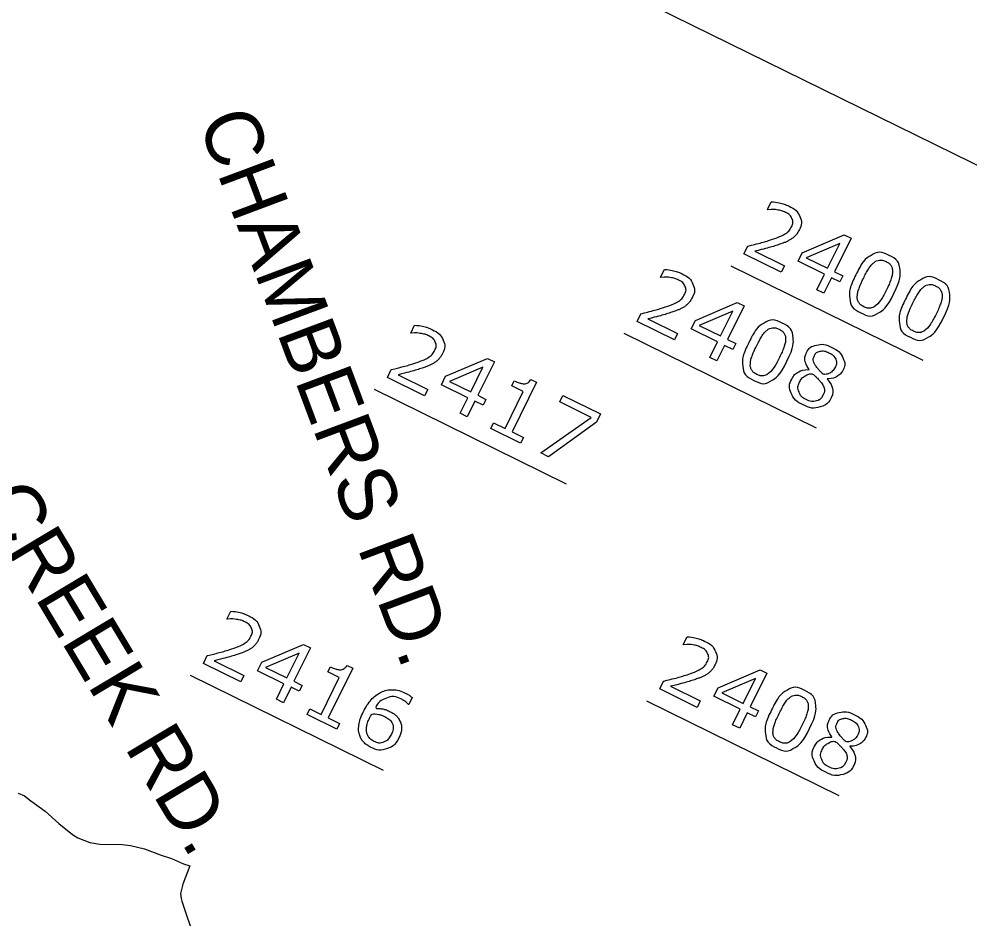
# Model space of a CAD drawing. Extents: x 1428128 to 1430390, y 857947 to 859822.
# Drawn here: x 1429189.4 to 1429305.6, y 859325.3 to 859435.3 of the extents above; entities that cross this region are included whole.
import ezdxf

# ---------------------------------------------------------------- set-up
doc = ezdxf.new("R2010")
doc.units = 0
doc.layers.add('Old_Level_1', color=7, linetype='Continuous')
doc.layers.add('Sheet Title CELL', color=7, linetype='Continuous')

msp = doc.modelspace()

# ---------------------------------------------------------------- linework, layer by layer
at = {"layer": 'Old_Level_1'}
for p, q in [((1429276.44, 859405.17), (1429299.9, 859393.63)), ((1429263.36, 859396.9), (1429286.88, 859385.33)), ((1429232.83, 859390.07), (1429256.32, 859378.51)), ((1429210.35, 859355.11), (1429233.92, 859343.51)), ((1429266.13, 859351.99), (1429289.65, 859340.41))]:
    msp.add_line(p, q, dxfattribs=at)
for points in [[(1429280.96, 859412.01), (1429280.92, 859412.03), (1429281.38, 859412.98)], [(1429289.75, 859403.2), (1429288.75, 859403.69), (1429287.82, 859401.8), (1429286.95, 859402.23), (1429287.89, 859404.12), (1429284.66, 859405.71), (1429285.17, 859406.75), (1429290.3, 859408.94), (1429291.13, 859408.53), (1429289.11, 859404.42), (1429290.11, 859403.93), (1429289.75, 859403.2)], [(1429288.24, 859404.85), (1429289.74, 859407.88), (1429285.63, 859406.13), (1429288.24, 859404.85)], [(1429282.6, 859404.37), (1429278.04, 859406.61), (1429278.51, 859407.56)], [(1429279.36, 859406.93), (1429282.99, 859405.15), (1429282.6, 859404.37)], [(1429267.89, 859403.74), (1429267.84, 859403.76), (1429268.31, 859404.71)], [(1429276.68, 859394.93), (1429275.68, 859395.42), (1429274.74, 859393.53), (1429273.88, 859393.96), (1429274.81, 859395.85), (1429271.58, 859397.44), (1429272.1, 859398.48), (1429277.22, 859400.67), (1429278.06, 859400.26), (1429276.03, 859396.15), (1429277.03, 859395.66), (1429276.68, 859394.93)], [(1429269.53, 859396.1), (1429264.97, 859398.34), (1429265.44, 859399.29)], [(1429266.29, 859398.66), (1429269.91, 859396.88), (1429269.53, 859396.1)], [(1429275.17, 859396.58), (1429276.66, 859399.62), (1429272.56, 859397.86), (1429275.17, 859396.58)], [(1429237.36, 859396.91), (1429237.31, 859396.93), (1429237.78, 859397.88)], [(1429246.15, 859388.1), (1429245.15, 859388.59), (1429244.21, 859386.7), (1429243.35, 859387.12), (1429244.28, 859389.02), (1429241.05, 859390.61), (1429241.57, 859391.65), (1429246.69, 859393.84), (1429247.53, 859393.43), (1429245.5, 859389.32), (1429246.5, 859388.83), (1429246.15, 859388.1)], [(1429244.64, 859389.75), (1429246.13, 859392.78), (1429242.03, 859391.03), (1429244.64, 859389.75)], [(1429239, 859389.26), (1429234.44, 859391.51), (1429234.91, 859392.46)], [(1429235.76, 859391.83), (1429239.38, 859390.04), (1429239, 859389.26)], [(1429285.99, 859392.46), (1429286.01, 859392.48)], [(1429250.74, 859383.49), (1429247.1, 859385.28), (1429247.43, 859385.97), (1429248.84, 859385.28), (1429251.05, 859389.79), (1429249.65, 859390.48), (1429249.96, 859391.09)], [(1429251.99, 859391.26), (1429252.69, 859390.91), (1429249.7, 859384.85), (1429251.08, 859384.17), (1429250.74, 859383.49)], [(1429288.23, 859391.35), (1429288.21, 859391.32)], [(1429260.02, 859386.03), (1429254.16, 859381.8), (1429253.19, 859382.28), (1429259.35, 859386.63), (1429255.52, 859388.51), (1429255.91, 859389.3), (1429260.51, 859387.04), (1429260.02, 859386.03)], [(1429214.88, 859361.95), (1429214.83, 859361.97), (1429215.3, 859362.92)], [(1429270.66, 859358.83), (1429270.61, 859358.85), (1429271.08, 859359.8)], [(1429223.67, 859353.14), (1429222.67, 859353.63), (1429221.73, 859351.74), (1429220.87, 859352.17), (1429221.8, 859354.06), (1429218.57, 859355.65), (1429219.08, 859356.69), (1429224.21, 859358.88), (1429225.04, 859358.47), (1429223.02, 859354.36), (1429224.02, 859353.87), (1429223.67, 859353.14)], [(1429216.52, 859354.31), (1429211.96, 859356.55), (1429212.43, 859357.5)], [(1429213.28, 859356.87), (1429216.9, 859355.09), (1429216.52, 859354.31)], [(1429222.15, 859354.79), (1429223.65, 859357.82), (1429219.54, 859356.07), (1429222.15, 859354.79)], [(1429228.26, 859348.53), (1429224.62, 859350.32), (1429224.95, 859351.01), (1429226.35, 859350.32), (1429228.57, 859354.83), (1429227.17, 859355.52), (1429227.48, 859356.13)], [(1429229.51, 859356.3), (1429230.21, 859355.95), (1429227.22, 859349.89), (1429228.6, 859349.21), (1429228.26, 859348.53)], [(1429279.45, 859350.02), (1429278.45, 859350.51), (1429277.52, 859348.62), (1429276.65, 859349.04), (1429277.58, 859350.94), (1429274.36, 859352.53), (1429274.87, 859353.56), (1429280, 859355.76), (1429280.83, 859355.35), (1429278.81, 859351.24), (1429279.81, 859350.74), (1429279.45, 859350.02)], [(1429272.3, 859351.18), (1429267.74, 859353.43), (1429268.21, 859354.38)], [(1429277.94, 859351.66), (1429279.43, 859354.7), (1429275.33, 859352.95), (1429277.94, 859351.66)], [(1429269.06, 859353.75), (1429272.68, 859351.96), (1429272.3, 859351.18)], [(1429237.47, 859352.38), (1429237.05, 859351.51), (1429237, 859351.53)], [(1429288.77, 859347.54), (1429288.78, 859347.57)], [(1429291, 859346.43), (1429290.98, 859346.41)]]:
    msp.add_lwpolyline(points, dxfattribs=at)
for points in [[(1429281.38, 859412.98), (1429281.78, 859412.98), (1429282.38, 859412.85), (1429282.98, 859412.71), (1429283.49, 859412.47), (1429284.52, 859411.96), (1429284.87, 859411.17), (1429285.21, 859410.38), (1429284.79, 859409.53), (1429284.6, 859409.14), (1429284.34, 859408.86), (1429284.08, 859408.57), (1429283.74, 859408.37), (1429283.43, 859408.18), (1429283.06, 859408.02), (1429282.69, 859407.87), (1429282.19, 859407.71), (1429281.47, 859407.47), (1429280.73, 859407.28), (1429280, 859407.09), (1429279.36, 859406.93)], [(1429278.51, 859407.56), (1429279.19, 859407.73), (1429279.87, 859407.9), (1429280.54, 859408.08), (1429281.15, 859408.28), (1429282.44, 859408.69), (1429283, 859409.02), (1429283.57, 859409.36), (1429283.85, 859409.93), (1429284.11, 859410.46), (1429283.91, 859410.92), (1429283.71, 859411.39), (1429283.08, 859411.7), (1429282.67, 859411.9), (1429282.12, 859411.99), (1429281.57, 859412.08), (1429280.96, 859412.01)], [(1429296.38, 859401.77), (1429295.48, 859399.96), (1429294.5, 859399.39), (1429293.51, 859398.82), (1429292.32, 859399.41), (1429291.11, 859400), (1429290.98, 859401.14), (1429290.84, 859402.27), (1429291.72, 859404.05), (1429292.6, 859405.85), (1429293.59, 859406.43), (1429294.58, 859407.01), (1429295.77, 859406.42), (1429296.98, 859405.83), (1429297.11, 859404.68), (1429297.24, 859403.53), (1429296.38, 859401.77)], [(1429294.18, 859400.3), (1429294.52, 859400.59), (1429294.82, 859401.06), (1429295.12, 859401.53), (1429295.46, 859402.22), (1429295.8, 859402.91), (1429295.99, 859403.45), (1429296.18, 859403.98), (1429296.19, 859404.41), (1429296.21, 859404.84), (1429296.02, 859405.15), (1429295.84, 859405.46), (1429295.41, 859405.67), (1429294.98, 859405.88), (1429294.62, 859405.84), (1429294.25, 859405.8), (1429293.91, 859405.53), (1429293.6, 859405.27), (1429293.27, 859404.76), (1429292.95, 859404.25), (1429292.64, 859403.6), (1429292.29, 859402.9), (1429292.11, 859402.4), (1429291.92, 859401.9), (1429291.9, 859401.44), (1429291.87, 859401.02), (1429292.06, 859400.7), (1429292.24, 859400.38), (1429292.69, 859400.15), (1429293.11, 859399.94), (1429293.48, 859399.98), (1429293.85, 859400.02), (1429294.18, 859400.3)], [(1429268.31, 859404.71), (1429268.71, 859404.71), (1429269.31, 859404.58), (1429269.91, 859404.45), (1429270.41, 859404.2), (1429271.45, 859403.69), (1429271.79, 859402.9), (1429272.13, 859402.11), (1429271.71, 859401.26), (1429271.52, 859400.87), (1429271.26, 859400.59), (1429271, 859400.31), (1429270.67, 859400.1), (1429270.35, 859399.91), (1429269.98, 859399.75), (1429269.61, 859399.6), (1429269.11, 859399.44), (1429268.39, 859399.2), (1429267.66, 859399.01), (1429266.92, 859398.82), (1429266.29, 859398.66)], [(1429265.44, 859399.29), (1429266.11, 859399.46), (1429266.79, 859399.64), (1429267.47, 859399.81), (1429268.08, 859400.01), (1429269.36, 859400.42), (1429269.93, 859400.75), (1429270.49, 859401.09), (1429270.77, 859401.66), (1429271.03, 859402.19), (1429270.83, 859402.66), (1429270.63, 859403.12), (1429270.01, 859403.43), (1429269.6, 859403.63), (1429269.04, 859403.72), (1429268.49, 859403.81), (1429267.89, 859403.74)], [(1429302.44, 859398.79), (1429301.55, 859396.98), (1429300.56, 859396.41), (1429299.58, 859395.84), (1429298.39, 859396.42), (1429297.17, 859397.02), (1429297.04, 859398.15), (1429296.91, 859399.29), (1429297.78, 859401.07), (1429298.67, 859402.87), (1429299.65, 859403.45), (1429300.64, 859404.03), (1429301.84, 859403.44), (1429303.05, 859402.84), (1429303.18, 859401.7), (1429303.31, 859400.55), (1429302.44, 859398.79)], [(1429300.24, 859397.32), (1429300.58, 859397.61), (1429300.88, 859398.08), (1429301.18, 859398.54), (1429301.52, 859399.24), (1429301.86, 859399.93), (1429302.05, 859400.46), (1429302.25, 859401), (1429302.26, 859401.43), (1429302.27, 859401.86), (1429302.08, 859402.17), (1429301.9, 859402.48), (1429301.47, 859402.69), (1429301.04, 859402.9), (1429300.68, 859402.86), (1429300.32, 859402.82), (1429299.98, 859402.54), (1429299.66, 859402.28), (1429299.34, 859401.77), (1429299.02, 859401.26), (1429298.7, 859400.62), (1429298.35, 859399.91), (1429298.17, 859399.41), (1429297.98, 859398.91), (1429297.96, 859398.46), (1429297.94, 859398.03), (1429298.12, 859397.71), (1429298.3, 859397.39), (1429298.75, 859397.17), (1429299.18, 859396.96), (1429299.54, 859397), (1429299.91, 859397.04), (1429300.24, 859397.32)], [(1429283.3, 859393.5), (1429282.41, 859391.69), (1429281.42, 859391.12), (1429280.44, 859390.55), (1429279.25, 859391.14), (1429278.04, 859391.73), (1429277.9, 859392.87), (1429277.77, 859394), (1429278.64, 859395.78), (1429279.53, 859397.58), (1429280.51, 859398.16), (1429281.5, 859398.74), (1429282.7, 859398.15), (1429283.91, 859397.56), (1429284.04, 859396.41), (1429284.17, 859395.26), (1429283.3, 859393.5)], [(1429237.78, 859397.88), (1429238.18, 859397.88), (1429238.78, 859397.75), (1429239.38, 859397.61), (1429239.88, 859397.37), (1429240.92, 859396.86), (1429241.26, 859396.07), (1429241.6, 859395.28), (1429241.18, 859394.43), (1429240.99, 859394.04), (1429240.73, 859393.76), (1429240.47, 859393.47), (1429240.14, 859393.27), (1429239.82, 859393.08), (1429239.45, 859392.92), (1429239.08, 859392.77), (1429238.58, 859392.61), (1429237.86, 859392.37), (1429237.13, 859392.18), (1429236.39, 859391.99), (1429235.76, 859391.83)], [(1429281.1, 859392.03), (1429281.44, 859392.32), (1429281.74, 859392.79), (1429282.04, 859393.26), (1429282.38, 859393.96), (1429282.72, 859394.64), (1429282.91, 859395.18), (1429283.11, 859395.71), (1429283.12, 859396.15), (1429283.13, 859396.57), (1429282.95, 859396.88), (1429282.76, 859397.19), (1429282.33, 859397.41), (1429281.91, 859397.61), (1429281.54, 859397.57), (1429281.18, 859397.53), (1429280.84, 859397.26), (1429280.52, 859397), (1429280.2, 859396.49), (1429279.88, 859395.98), (1429279.56, 859395.33), (1429279.21, 859394.63), (1429279.03, 859394.13), (1429278.84, 859393.63), (1429278.82, 859393.17), (1429278.8, 859392.75), (1429278.98, 859392.43), (1429279.16, 859392.11), (1429279.61, 859391.88), (1429280.04, 859391.68), (1429280.4, 859391.71), (1429280.77, 859391.75), (1429281.1, 859392.03)], [(1429234.91, 859392.46), (1429235.58, 859392.63), (1429236.26, 859392.8), (1429236.94, 859392.98), (1429237.55, 859393.17), (1429238.83, 859393.59), (1429239.4, 859393.92), (1429239.96, 859394.26), (1429240.24, 859394.83), (1429240.5, 859395.36), (1429240.3, 859395.82), (1429240.1, 859396.29), (1429239.48, 859396.6), (1429239.07, 859396.8), (1429238.51, 859396.89), (1429237.96, 859396.98), (1429237.36, 859396.91)], [(1429286.01, 859392.48), (1429285.61, 859393.04), (1429285.52, 859393.51), (1429285.42, 859393.98), (1429285.68, 859394.5), (1429286.05, 859395.26), (1429286.92, 859395.46), (1429287.8, 859395.66), (1429288.76, 859395.18), (1429289.77, 859394.69), (1429290.13, 859393.91), (1429290.5, 859393.13), (1429290.13, 859392.38), (1429289.9, 859391.93), (1429289.4, 859391.62), (1429288.9, 859391.32), (1429288.23, 859391.35)], [(1429289.23, 859392.81), (1429289.47, 859393.29), (1429289.24, 859393.76), (1429289.01, 859394.24), (1429288.43, 859394.52), (1429287.86, 859394.8), (1429287.36, 859394.71), (1429286.86, 859394.62), (1429286.64, 859394.16), (1429286.48, 859393.83), (1429286.54, 859393.5), (1429286.61, 859393.18), (1429286.89, 859392.81), (1429287.02, 859392.64), (1429287.27, 859392.36), (1429287.52, 859392.07), (1429287.77, 859391.84), (1429288.37, 859391.92), (1429288.7, 859392.15), (1429289.03, 859392.39), (1429289.23, 859392.81)], [(1429288.69, 859389), (1429288.26, 859388.13), (1429287.29, 859387.88), (1429286.33, 859387.64), (1429285.3, 859388.15), (1429284.2, 859388.68), (1429283.83, 859389.57), (1429283.46, 859390.45), (1429283.9, 859391.33), (1429284.17, 859391.89), (1429284.72, 859392.19), (1429285.27, 859392.48), (1429285.99, 859392.46)], [(1429287.72, 859389.37), (1429287.92, 859389.79), (1429287.86, 859390.13), (1429287.8, 859390.47), (1429287.39, 859390.98), (1429287.23, 859391.19), (1429287.02, 859391.4), (1429286.81, 859391.61), (1429286.46, 859391.97), (1429285.95, 859391.95), (1429285.51, 859391.69), (1429285.08, 859391.43), (1429284.85, 859390.95), (1429284.55, 859390.34), (1429284.77, 859389.74), (1429285, 859389.13), (1429285.64, 859388.81), (1429286.3, 859388.49), (1429286.87, 859388.63), (1429287.43, 859388.78), (1429287.72, 859389.37)], [(1429249.96, 859391.09), (1429250.24, 859390.95), (1429250.59, 859390.84), (1429250.94, 859390.73), (1429251.15, 859390.73), (1429251.41, 859390.74), (1429251.62, 859390.86), (1429251.82, 859390.97), (1429251.99, 859391.26)], [(1429288.21, 859391.32), (1429288.71, 859390.74), (1429288.85, 859390.17), (1429288.99, 859389.61), (1429288.69, 859389)], [(1429215.3, 859362.92), (1429215.7, 859362.92), (1429216.3, 859362.79), (1429216.9, 859362.65), (1429217.4, 859362.41), (1429218.44, 859361.9), (1429218.78, 859361.11), (1429219.12, 859360.32), (1429218.7, 859359.47), (1429218.51, 859359.08), (1429218.25, 859358.8), (1429217.99, 859358.51), (1429217.65, 859358.31), (1429217.34, 859358.12), (1429216.97, 859357.96), (1429216.6, 859357.81), (1429216.1, 859357.65), (1429215.38, 859357.41), (1429214.65, 859357.22), (1429213.91, 859357.03), (1429213.28, 859356.87)], [(1429212.43, 859357.5), (1429213.1, 859357.67), (1429213.78, 859357.84), (1429214.46, 859358.02), (1429215.07, 859358.21), (1429216.35, 859358.63), (1429216.91, 859358.96), (1429217.48, 859359.3), (1429217.76, 859359.87), (1429218.02, 859360.4), (1429217.82, 859360.86), (1429217.62, 859361.33), (1429217, 859361.64), (1429216.58, 859361.84), (1429216.03, 859361.93), (1429215.48, 859362.02), (1429214.88, 859361.95)], [(1429271.08, 859359.8), (1429271.48, 859359.8), (1429272.08, 859359.67), (1429272.68, 859359.53), (1429273.18, 859359.29), (1429274.22, 859358.78), (1429274.56, 859357.99), (1429274.9, 859357.2), (1429274.48, 859356.34), (1429274.3, 859355.96), (1429274.04, 859355.68), (1429273.77, 859355.39), (1429273.44, 859355.19), (1429273.12, 859354.99), (1429272.75, 859354.84), (1429272.38, 859354.69), (1429271.88, 859354.52), (1429271.16, 859354.29), (1429270.43, 859354.1), (1429269.69, 859353.91), (1429269.06, 859353.75)], [(1429268.21, 859354.38), (1429268.88, 859354.55), (1429269.56, 859354.72), (1429270.24, 859354.89), (1429270.85, 859355.09), (1429272.13, 859355.51), (1429272.7, 859355.84), (1429273.26, 859356.18), (1429273.55, 859356.75), (1429273.8, 859357.28), (1429273.6, 859357.74), (1429273.4, 859358.21), (1429272.78, 859358.51), (1429272.37, 859358.72), (1429271.82, 859358.81), (1429271.26, 859358.9), (1429270.66, 859358.83)], [(1429227.48, 859356.13), (1429227.76, 859355.99), (1429228.11, 859355.88), (1429228.46, 859355.77), (1429228.67, 859355.77), (1429228.93, 859355.79), (1429229.14, 859355.9), (1429229.34, 859356.02), (1429229.51, 859356.3)], [(1429235.88, 859347.49), (1429235.37, 859346.46), (1429234.38, 859346.14), (1429233.38, 859345.83), (1429232.4, 859346.31), (1429231.91, 859346.56), (1429231.57, 859346.91), (1429231.24, 859347.26), (1429231.08, 859347.72), (1429230.88, 859348.29), (1429230.97, 859349.01), (1429231.07, 859349.73), (1429231.49, 859350.6), (1429231.94, 859351.5), (1429232.47, 859352.1), (1429233, 859352.69), (1429233.69, 859353.02), (1429234.33, 859353.34), (1429235.1, 859353.32), (1429235.87, 859353.3), (1429236.71, 859352.88), (1429236.98, 859352.75), (1429237.15, 859352.64), (1429237.32, 859352.53), (1429237.47, 859352.38)], [(1429286.07, 859348.59), (1429285.18, 859346.78), (1429284.2, 859346.21), (1429283.21, 859345.64), (1429282.02, 859346.22), (1429280.81, 859346.82), (1429280.67, 859347.95), (1429280.54, 859349.09), (1429281.42, 859350.87), (1429282.3, 859352.67), (1429283.29, 859353.25), (1429284.27, 859353.83), (1429285.47, 859353.24), (1429286.68, 859352.64), (1429286.81, 859351.5), (1429286.94, 859350.35), (1429286.07, 859348.59)], [(1429237, 859351.53), (1429236.91, 859351.66), (1429236.68, 859351.85), (1429236.46, 859352.04), (1429236.19, 859352.17), (1429235.22, 859352.65), (1429234.34, 859352.32), (1429233.47, 859352), (1429232.86, 859351.01), (1429233.36, 859351.06), (1429233.78, 859351), (1429234.21, 859350.93), (1429234.69, 859350.7), (1429235.12, 859350.49), (1429235.41, 859350.25), (1429235.7, 859350.01), (1429235.92, 859349.6), (1429236.18, 859349.13), (1429236.18, 859348.61), (1429236.17, 859348.09), (1429235.88, 859347.49)], [(1429283.87, 859347.12), (1429284.21, 859347.41), (1429284.51, 859347.88), (1429284.81, 859348.35), (1429285.16, 859349.04), (1429285.49, 859349.73), (1429285.69, 859350.27), (1429285.88, 859350.8), (1429285.89, 859351.23), (1429285.9, 859351.66), (1429285.72, 859351.97), (1429285.53, 859352.28), (1429285.1, 859352.49), (1429284.68, 859352.7), (1429284.31, 859352.66), (1429283.95, 859352.62), (1429283.61, 859352.34), (1429283.29, 859352.08), (1429282.97, 859351.57), (1429282.65, 859351.06), (1429282.33, 859350.42), (1429281.99, 859349.71), (1429281.8, 859349.21), (1429281.62, 859348.72), (1429281.59, 859348.26), (1429281.57, 859347.83), (1429281.75, 859347.51), (1429281.93, 859347.19), (1429282.39, 859346.97), (1429282.81, 859346.76), (1429283.18, 859346.8), (1429283.54, 859346.84), (1429283.87, 859347.12)], [(1429234.94, 859347.9), (1429235.15, 859348.32), (1429235.16, 859348.65), (1429235.17, 859348.99), (1429234.99, 859349.33), (1429234.85, 859349.58), (1429234.62, 859349.75), (1429234.39, 859349.92), (1429234.11, 859350.05), (1429233.73, 859350.24), (1429233.36, 859350.32), (1429232.98, 859350.39), (1429232.54, 859350.37), (1429232.48, 859350.27), (1429232.43, 859350.18), (1429232.38, 859350.09), (1429232.31, 859349.95), (1429231.96, 859349.24), (1429231.91, 859348.76), (1429231.85, 859348.27), (1429231.99, 859347.9), (1429232.1, 859347.6), (1429232.3, 859347.39), (1429232.49, 859347.18), (1429232.78, 859347.04), (1429233.43, 859346.72), (1429234, 859346.93), (1429234.57, 859347.15), (1429234.94, 859347.9)], [(1429288.78, 859347.57), (1429288.38, 859348.13), (1429288.29, 859348.6), (1429288.2, 859349.07), (1429288.45, 859349.59), (1429288.82, 859350.35), (1429289.7, 859350.54), (1429290.57, 859350.74), (1429291.53, 859350.27), (1429292.54, 859349.77), (1429292.9, 859348.99), (1429293.27, 859348.21), (1429292.9, 859347.47), (1429292.68, 859347.01), (1429292.17, 859346.71), (1429291.67, 859346.41), (1429291, 859346.43)], [(1429292.01, 859347.9), (1429292.24, 859348.38), (1429292.01, 859348.85), (1429291.78, 859349.32), (1429291.2, 859349.61), (1429290.63, 859349.89), (1429290.13, 859349.8), (1429289.63, 859349.7), (1429289.41, 859349.24), (1429289.25, 859348.92), (1429289.31, 859348.59), (1429289.38, 859348.26), (1429289.66, 859347.9), (1429289.79, 859347.73), (1429290.04, 859347.45), (1429290.29, 859347.16), (1429290.54, 859346.93), (1429291.14, 859347), (1429291.47, 859347.24), (1429291.8, 859347.48), (1429292.01, 859347.9)], [(1429291.46, 859344.08), (1429291.03, 859343.21), (1429290.07, 859342.97), (1429289.1, 859342.73), (1429288.07, 859343.23), (1429286.98, 859343.77), (1429286.6, 859344.66), (1429286.23, 859345.54), (1429286.67, 859346.42), (1429286.94, 859346.98), (1429287.49, 859347.28), (1429288.04, 859347.57), (1429288.77, 859347.54)], [(1429290.49, 859344.46), (1429290.7, 859344.87), (1429290.64, 859345.21), (1429290.58, 859345.55), (1429290.17, 859346.07), (1429290, 859346.27), (1429289.79, 859346.48), (1429289.58, 859346.69), (1429289.23, 859347.06), (1429288.72, 859347.03), (1429288.29, 859346.78), (1429287.85, 859346.52), (1429287.62, 859346.04), (1429287.32, 859345.43), (1429287.54, 859344.82), (1429287.77, 859344.22), (1429288.42, 859343.9), (1429289.08, 859343.58), (1429289.64, 859343.72), (1429290.2, 859343.87), (1429290.49, 859344.46)], [(1429290.98, 859346.41), (1429291.49, 859345.82), (1429291.62, 859345.26), (1429291.76, 859344.7), (1429291.46, 859344.08)]]:
    msp.add_open_spline(points, degree=3, dxfattribs=at)
at = {"layer": 'Sheet Title CELL'}
msp.add_line((1429080.28, 859528.78), (1429358.43, 859391.92), dxfattribs=at)
for points in [[(1429189.3, 859340.67), (1429190.08, 859340.35), (1429190.87, 859339.74), (1429192.6, 859338.48), (1429194.28, 859337)], [(1429194.28, 859337), (1429195.93, 859335.65), (1429196.6, 859335.23)], [(1429196.6, 859335.23), (1429198.07, 859334.67), (1429199.29, 859334.47), (1429202.01, 859334.42), (1429203.05, 859334.31), (1429204.75, 859333.88), (1429206.79, 859333.13), (1429208.05, 859332.7), (1429209.52, 859332.07), (1429210.31, 859331.79)], [(1429210.31, 859331.79), (1429209.42, 859329.56), (1429209.14, 859328.42), (1429209.22, 859327.81), (1429209.33, 859327.48)], [(1429209.33, 859327.48), (1429210.88, 859322.87)]]:
    msp.add_lwpolyline(points, dxfattribs=at)

# ---------------------------------------------------------------- texts
at = {"layer": 'Old_Level_1'}
for s, rotation, p in [('CHAMBERS RD.', 290.5122, (1429211.25, 859422.84)), ('CREEK RD.', 300.914, (1429184.33, 859376.23))]:
    msp.add_text(s, height=7, rotation=rotation, dxfattribs=at).set_placement(p)

doc.saveas('drawing.dxf')
